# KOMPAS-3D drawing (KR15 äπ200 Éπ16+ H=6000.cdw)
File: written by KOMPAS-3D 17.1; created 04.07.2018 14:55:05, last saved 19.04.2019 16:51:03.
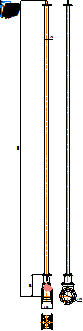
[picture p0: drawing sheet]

Sheet 1: A4, portrait

Title block, sheet 1: name: KR15 Ду200 Ру16+ / H=6000; material: Внимание! Данный продукт является объектом авторского права ООО «Торговый Дом АДЛ». / Запрещается изменение, копирование, распространение / (в том числе путем копирования на другие сайты и ресурсы в Интернете) / или любое иное использование информации и объектов без предварительного / согласия правообладателя (ООО «Торговый Дом АДЛ»).; mass: 36,7; sheets: 1; organisation: ООО "Торговый дом АДЛ"; sheet format: A4; stored path: \\adlc.lan\data\АДЛ_ПКД\3D-модели\ADL production\Клиновые задвижки серии KR ГРАНАР\Клиновые задвижки KR15 со стационарным удлинением\KOMPAS 2D\KR15 Ду200 Ру16+ H=6000.cdw

Views: Проекционный вид 6, Проекционный вид 12, Проекционный вид 14
Referenced files in C:\Users\kka\KOMPAS_Work\Удлинения БИВАЛ ф. ADL\!Задвижки\У_ду_125-400\: Ушду125-400.a3d
Referenced files in C:\Users\kka\KOMPAS_Work\!Trash\ГРАНАР KR Задвижки с приводами и удлинениями\С приводами\: KR15 Ду200 Ру16.m3d
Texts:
  kka
  adl
  УШКЗ.100000.00.00
  Удлинение клиновой задвижки с редуктором
  Крепежное изделие ГОСТ
  Болт
  ГОСТ
  Гайка
  Лит-Масса-Масштаб
  Материал-Предприятие
  Title Specification
  Body Specification ( left align )
  Body Specificaton ( centered )
  Поз.
  Кол.
  Приме-
  чание
  Таблица спецификации
Dimensions and other numbers on the sheet: 6000; 76; 230; 430; 4; 1; 58; 40Х; 019; 1:1; 36,7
